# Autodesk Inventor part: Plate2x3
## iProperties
Created: 2006-02
Part Number: Plate2x3
Material: Stainless Steel
Document SubType Name: Modeling
Designer: 40664
Mass: 200889 g
Surface Area: 50370 cm^2
Volume: 24862.5 cm^3
Density: 8.08 g/cm^3
CSToolsMass: 201.0
CSToolsVolume: 24862500.0
CSToolsArea: 50370.0
Author: 40664
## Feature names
1. Extrusion2
